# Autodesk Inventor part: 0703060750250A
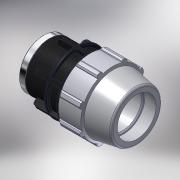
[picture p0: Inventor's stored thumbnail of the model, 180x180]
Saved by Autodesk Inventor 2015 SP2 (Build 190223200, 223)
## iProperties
Created: 2017-02
Part Number: 0703060750250A
Material: PVC-Piping
Description: PLASSON FEMALE ADAPTOR 75-2.1/2"
Document SubType Name: Modeling
Designer: KIM
Mass: 92.6774 g
Surface Area: 199.44 cm^2
Volume: 66.1981 cm^3
Density: 1.4 g/cm^3
Appearance: PTFE
Author: KIM
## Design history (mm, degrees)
derived "87030.ipt"
feature "Solid1::87030.ipt"
tag "TaggingFeature1"
body "Solid1"
other parameters: "d2" = 75, "d4" = 24.28571, "d5" = 42.5, "d7" = 132, "d9" = 24.28571, "d11" = 4.85714, "d12" = 105.6, "d13" = 120 deg, "d14" = 97.5, "d15" = 10 deg, "d16" = 118.8, "d18" = 3.75, "d19" = 35 deg, "d20" = 17.5 deg, "d21" = 122.76, "d23" = 0, "d25" = 360 deg, "d27" = 2.64, "d34" = 6.6, "d35" = 51, "d36" = 0, "d42" = 42.5, "d43" = 3.96, "d46" = 2.25, "d49" = 132, "d53" = 1.5, "d55" = 360 deg, "d61" = 33, "d63" = 72.226, "d64" = 56.66667, "d65" = 6.6, "d69" = 95.04, "d70" = 3.3, "d71" = 12.6, "d72" = 0.5, "d73" = 1, "d_" = 75, "E_" = 132, "l_" = 132, "l_2" = 33, "Rp_Rc_" = 72.226
